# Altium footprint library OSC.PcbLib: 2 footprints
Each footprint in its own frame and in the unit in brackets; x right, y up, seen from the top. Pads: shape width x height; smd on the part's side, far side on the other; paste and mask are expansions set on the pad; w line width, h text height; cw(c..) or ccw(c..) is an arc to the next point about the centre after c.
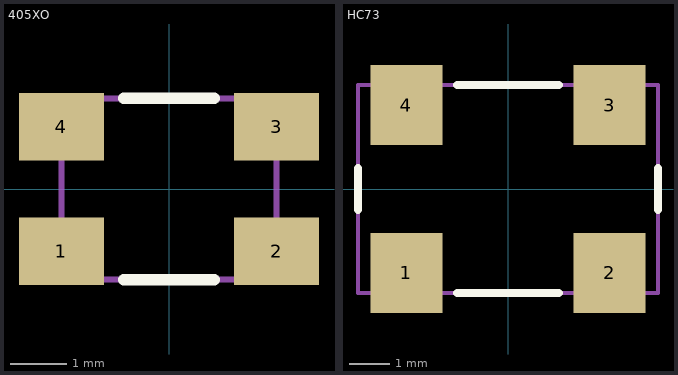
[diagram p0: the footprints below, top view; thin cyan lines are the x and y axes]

## 405XO [mm] "CTS 405 Series Crystal Oscillator"
height 1
pads (4):
  rect 1.5x1.2 smd: 1(-1.9,-1.1) 2(1.9,-1.1) 3(1.9,1.1) 4(-1.9,1.1)
Top Overlay:
  lines w0.203: -0.8,-1.6 0.8,-1.6 ; -0.8,1.6 0.8,1.6
Mechanical 31:
  lines w0.102: -1.9,-1.6 1.9,-1.6 1.9,1.6 -1.9,1.6 -1.9,-1.6
  text ".Comment" at -1.5,-0.75 h0.51
  text ".Designator" at -1.5,0.25 h0.51
3D body "User Library-CTS.step": height 1.07, standoff 0.3, extent -1.6,-1.25 1.6,1.25

## HC73 [mm] "FXO HC73 Series Oscillator"
height 1.4
pads (4):
  rect 1.8x2 smd: 1(-2.54,-2.1) 2(2.54,-2.1) 3(2.54,2.1) 4(-2.54,2.1)
Top Overlay:
  lines w0.203: -3.75,-0.52 -3.75,0.52 ; -1.27,-2.6 1.27,-2.6 ; -1.27,2.6 1.27,2.6 ; 3.75,-0.52 3.75,0.52
Mechanical 31:
  lines w0.102: -3.75,-2.6 3.75,-2.6 3.75,2.6 -3.75,2.6 -3.75,-2.6
  text ".Comment" at -3,-1 h0.76
  text ".Designator" at -3,0.5 h0.76
3D body "User Library-FXO-HC73.step": height 1.4, standoff -0.01, extent -3.75,-2.62 3.75,2.6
